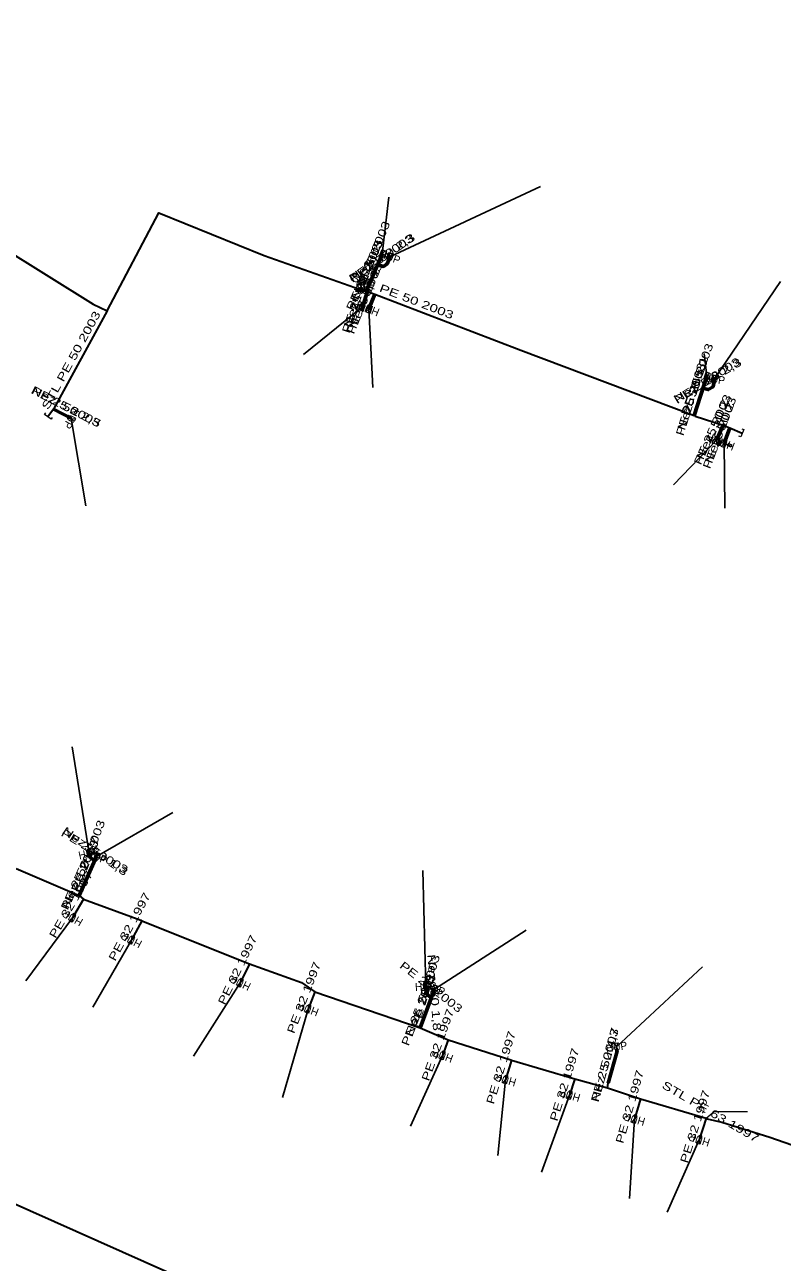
# Model space of a CAD drawing. Extents: x -737484 to -734496, y -1033882 to -1030666.
# Drawn here: x -736052.2 to -735957.6, y -1032940.7 to -1032786.1 of the extents above; entities that cross this region are included whole.
import ezdxf
from ezdxf.enums import TextEntityAlignment as Align

# ---------------------------------------------------------------- set-up
doc = ezdxf.new("R2010")
doc.units = 0
doc.header["$LTSCALE"] = 0.4
for name, color, linetype, lineweight in [('1', 7, 'Continuous', 13), ('18', 7, 'Continuous', 60), ('22', 7, 'Continuous', 25), ('5', 7, 'Continuous', 35), ('7', 7, 'Continuous', 35)]:
    doc.layers.add(name, color=color, linetype=linetype, lineweight=lineweight)
doc.layers.add('2', color=7, linetype='Continuous')

msp = doc.modelspace()

# ---------------------------------------------------------------- linework, layer by layer
at = {"layer": '1'}
for p, q in [((-735964.888, -1032838.359), (-735964.421, -1032838.538)), ((-735964.378, -1032838.635), (-735964.051, -1032838.76)), ((-736001.597, -1032906.297), (-736001.932, -1032906.194)), ((-736001.07, -1032906.537), (-736001.548, -1032906.39))]:
    msp.add_line(p, q, dxfattribs=at)
for points in [[(-736007.586, -1032814.183), (-736007.215, -1032814.333), (-736007.96, -1032815.11), (-736007.589, -1032815.26)], [(-736006.651, -1032814.541), (-736006.278, -1032814.684), (-736007.009, -1032815.475), (-736006.636, -1032815.618)], [(-736010.022, -1032821.856), (-736010.402, -1032821.732), (-736009.713, -1032820.905), (-736010.093, -1032820.781)], [(-736009.264, -1032822.103), (-736009.635, -1032821.953), (-736008.89, -1032821.176), (-736009.261, -1032821.026)], [(-735967.089, -1032829.456), (-735966.711, -1032829.586), (-735967.414, -1032830.401), (-735967.036, -1032830.531)], [(-735966.24, -1032829.832), (-735965.844, -1032829.887), (-735966.379, -1032830.822), (-735965.983, -1032830.877)], [(-736045.891, -1032835.303), (-736046.073, -1032835.66), (-736046.782, -1032834.849), (-736046.964, -1032835.206)], [(-735965.856, -1032838.527), (-735966.222, -1032838.364), (-735965.449, -1032837.613), (-735965.815, -1032837.45)], [(-735964.879, -1032838.897), (-735965.252, -1032838.754), (-735964.521, -1032837.963), (-735964.894, -1032837.82)], [(-735963.954, -1032838.717), (-735964.008, -1032838.857), (-735964.474, -1032838.678), (-735964.421, -1032838.538)], [(-735964.003, -1032838.738), (-735964.03, -1032838.808), (-735964.426, -1032838.656), (-735964.399, -1032838.585)], [(-735963.954, -1032838.717), (-735963.9, -1032838.577), (-735964.367, -1032838.398), (-735964.421, -1032838.538)], [(-736044.524, -1032889.134), (-736044.134, -1032889.044), (-736044.299, -1032890.109), (-736043.909, -1032890.019)], [(-736043.278, -1032889.446), (-736042.905, -1032889.589), (-736043.636, -1032890.38), (-736043.263, -1032890.523)], [(-736046.355, -1032898.168), (-736046.702, -1032897.968), (-736045.855, -1032897.301), (-736046.202, -1032897.101)], [(-736038.977, -1032900.942), (-736039.33, -1032900.754), (-736038.507, -1032900.059), (-736038.86, -1032899.871)], [(-736025.366, -1032906.287), (-736025.725, -1032906.111), (-736024.928, -1032905.388), (-736025.287, -1032905.212)], [(-736002.388, -1032905.717), (-736001.989, -1032905.696), (-736002.336, -1032906.715), (-736001.937, -1032906.694)], [(-736001.114, -1032905.999), (-736000.731, -1032906.116), (-736001.406, -1032906.955), (-736001.023, -1032907.072)], [(-736002.026, -1032906.244), (-736002.07, -1032906.388), (-736001.592, -1032906.534), (-736001.548, -1032906.39)], [(-736002.026, -1032906.244), (-736001.982, -1032906.101), (-736001.504, -1032906.247), (-736001.548, -1032906.39)], [(-736001.979, -1032906.22), (-736001.957, -1032906.148), (-736001.55, -1032906.272), (-736001.572, -1032906.344)], [(-736016.844, -1032909.567), (-736017.217, -1032909.424), (-736016.486, -1032908.633), (-736016.859, -1032908.49)], [(-735978.595, -1032913.288), (-735978.199, -1032913.233), (-735978.456, -1032914.278), (-735978.06, -1032914.223)], [(-736000.042, -1032915.372), (-736000.417, -1032915.235), (-735999.7, -1032914.432), (-736000.075, -1032914.295)], [(-735992.136, -1032918.394), (-735992.519, -1032918.277), (-735991.844, -1032917.438), (-735992.227, -1032917.321)], [(-735984.137, -1032920.326), (-735984.52, -1032920.209), (-735983.845, -1032919.37), (-735984.228, -1032919.253)], [(-735976.031, -1032923.319), (-735976.416, -1032923.209), (-735975.755, -1032922.358), (-735976.14, -1032922.248)], [(-735967.948, -1032925.892), (-735968.328, -1032925.768), (-735967.639, -1032924.941), (-735968.019, -1032924.817)]]:
    msp.add_lwpolyline(points, close=True, dxfattribs=at)
for points in [[(-736048.814, -1032835.155), (-736048.964, -1032835.354), (-736049.763, -1032834.753), (-736049.612, -1032834.553)], [(-735962.657, -1032836.542), (-735962.427, -1032836.639), (-735962.818, -1032837.56), (-735963.048, -1032837.462)], [(-735967.14, -1032922.68), (-735966.134, -1032921.843), (-735961.961, -1032921.843)]]:
    msp.add_lwpolyline(points, dxfattribs=at)
at = {"layer": '18'}
for p, q in [((-736009.584, -1032819.381), (-736007.587, -1032814.721)), ((-736009.424, -1032819.415), (-736010.058, -1032821.319)), ((-736008.502, -1032819.728), (-736009.262, -1032821.565)), ((-735968.646, -1032834.879), (-735967.062, -1032829.994)), ((-736048.66, -1032834.104), (-736046.427, -1032835.255)), ((-735964.999, -1032836.113), (-735965.836, -1032837.989)), ((-735964.169, -1032836.447), (-735964.887, -1032838.359)), ((-736045.451, -1032894.832), (-736043.271, -1032889.985)), ((-736002.865, -1032911.396), (-736001.069, -1032906.536)), ((-735979.376, -1032918.271), (-735978.255, -1032914.276))]:
    msp.add_line(p, q, dxfattribs=at)
for points in [[(-736008.104, -1032816.084), (-736007.449, -1032816.274), (-736006.957, -1032815.939), (-736006.571, -1032814.963)], [(-735967.595, -1032831.464), (-735966.866, -1032831.643), (-735966.274, -1032831.294), (-735966.105, -1032830.289)], [(-736043.517, -1032890.496), (-736044.045, -1032890.131), (-736044.217, -1032889.576)], [(-736001.474, -1032907.613), (-736002.092, -1032907.095), (-736002.162, -1032906.205)]]:
    msp.add_lwpolyline(points, dxfattribs=at)
at = {"layer": '22'}
for p, q in [((-736006.644, -1032815.08), (-735987.84, -1032806.299)), ((-736007.588, -1032814.722), (-736006.781, -1032807.638)), ((-735966.112, -1032830.355), (-735957.857, -1032818.162)), ((-736010.058, -1032821.319), (-736017.442, -1032827.262)), ((-736009.263, -1032821.565), (-736008.771, -1032831.391)), ((-735967.063, -1032829.994), (-735967.368, -1032827.153)), ((-736046.428, -1032835.255), (-736044.61, -1032846.162)), ((-735965.836, -1032837.989), (-735971.199, -1032843.571)), ((-735964.887, -1032838.359), (-735964.799, -1032846.461)), ((-736044.217, -1032889.577), (-736046.313, -1032876.273)), ((-736043.271, -1032889.985), (-736033.77, -1032884.469)), ((-736002.163, -1032906.206), (-736002.514, -1032891.732)), ((-736046.279, -1032897.635), (-736052.127, -1032905.491)), ((-736001.069, -1032906.536), (-735989.632, -1032899.175)), ((-736038.92, -1032900.408), (-736043.748, -1032908.787)), ((-735978.328, -1032913.756), (-735967.59, -1032903.755)), ((-736025.328, -1032905.75), (-736031.18, -1032914.908)), ((-736016.853, -1032909.029), (-736020.071, -1032920.088)), ((-736000.059, -1032914.835), (-736004.066, -1032923.667)), ((-735992.183, -1032917.859), (-735993.145, -1032927.34)), ((-735984.183, -1032919.791), (-735987.707, -1032929.412)), ((-735976.086, -1032922.785), (-735976.692, -1032932.708)), ((-735967.985, -1032925.356), (-735971.985, -1032934.403))]:
    msp.add_line(p, q, dxfattribs=at)
at = {"layer": '5'}
msp.add_line((-735967.14, -1032922.68), (-735967.02, -1032922.75), dxfattribs=at)
for points in [[(-736164.978, -1032743.294), (-736163.22, -1032744.622), (-736144.295, -1032756.82), (-736143.663, -1032757.201), (-736143.285, -1032757.399), (-736123.669, -1032770.149), (-736106.324, -1032781.201), (-736106.054, -1032781.318), (-736105.301, -1032781.762), (-736097.333, -1032786.842), (-736084.708, -1032795.224), (-736075.443, -1032801.061), (-736071.322, -1032803.858), (-736070.031, -1032804.587), (-736068.124, -1032805.517), (-736067.175, -1032806.115), (-736055.501, -1032813.666), (-736043.698, -1032820.973), (-736041.939, -1032821.797)], [(-736041.939, -1032821.797), (-736035.48, -1032809.592), (-736022.335, -1032814.913), (-736009.585, -1032819.382), (-736009.425, -1032819.416), (-736008.503, -1032819.729), (-735990.294, -1032826.724), (-735968.647, -1032834.88), (-735968.483, -1032834.98), (-735965, -1032836.114), (-735964.169, -1032836.448), (-735962.623, -1032837.1)], [(-736041.939, -1032821.797), (-736048.661, -1032834.105), (-736049.364, -1032835.054)], [(-736235.45, -1032828.77), (-736180.2, -1032864.22), (-736120.57, -1032899.77), (-736068.64, -1032926.61), (-736000.29, -1032957.08), (-736038.27, -1033017.25), (-736040.52, -1033020.79), (-736047.44, -1033030.09), (-736048.2, -1033031.22)], [(-736053.32, -1032891.49), (-736045.452, -1032894.832), (-736044.92, -1032895.29), (-736037.75, -1032897.91), (-736037.64, -1032898.03), (-736024.19, -1032903.4), (-736017.69, -1032905.72), (-736016.03, -1032906.89), (-736002.866, -1032911.397), (-735999.35, -1032912.86), (-735991.54, -1032915.39), (-735991.43, -1032915.42), (-735983.55, -1032917.74), (-735979.44, -1032918.854), (-735975.35, -1032920.24), (-735967.14, -1032922.68)], [(-735967.14, -1032922.68), (-735967.02, -1032922.75), (-735965.176, -1032923.15), (-735959.158, -1032925.019), (-735949.736, -1032928.317), (-735941.277, -1032931.246), (-735939.362, -1032931.893), (-735921.803, -1032937.993), (-735921.819, -1032938.099)]]:
    msp.add_lwpolyline(points, dxfattribs=at)
at = {"layer": '7'}
for p, q in [((-736008.167, -1032816.154), (-736007.588, -1032814.722)), ((-736009.585, -1032819.382), (-736008.167, -1032816.154)), ((-736009.425, -1032819.416), (-736010.058, -1032821.319)), ((-736008.503, -1032819.729), (-736009.263, -1032821.565)), ((-735967.57, -1032831.427), (-735967.063, -1032829.994)), ((-735968.647, -1032834.88), (-735967.57, -1032831.427)), ((-736048.661, -1032834.105), (-736046.428, -1032835.255)), ((-735965, -1032836.114), (-735965.836, -1032837.989)), ((-735964.169, -1032836.448), (-735964.887, -1032838.359)), ((-736045.452, -1032894.832), (-736043.471, -1032890.516)), ((-736043.471, -1032890.516), (-736043.271, -1032889.985)), ((-736044.92, -1032895.29), (-736046.279, -1032897.635)), ((-736037.64, -1032898.03), (-736038.919, -1032900.407)), ((-736024.19, -1032903.4), (-736025.327, -1032905.75)), ((-736016.03, -1032906.89), (-736016.852, -1032909.029)), ((-736001.392, -1032907.619), (-736001.069, -1032906.536)), ((-736002.866, -1032911.397), (-736001.392, -1032907.619)), ((-735999.35, -1032912.86), (-736000.059, -1032914.834)), ((-735991.43, -1032915.42), (-735992.182, -1032917.858)), ((-735983.55, -1032917.74), (-735984.183, -1032919.79)), ((-735975.35, -1032920.24), (-735976.086, -1032922.784)), ((-735967.14, -1032922.68), (-735967.984, -1032925.355))]:
    msp.add_line(p, q, dxfattribs=at)
for points in [[(-736008.167, -1032816.154), (-736007.536, -1032816.344), (-736006.98, -1032815.959), (-736006.644, -1032815.08)], [(-735967.57, -1032831.427), (-735966.821, -1032831.594), (-735966.232, -1032831.22), (-735966.112, -1032830.355)], [(-736043.471, -1032890.516), (-736044.081, -1032890.151), (-736044.217, -1032889.577)], [(-736001.392, -1032907.619), (-736002.111, -1032907.063), (-736002.163, -1032906.206)], [(-735979.44, -1032918.854), (-735979.377, -1032918.272), (-735978.256, -1032914.277), (-735978.328, -1032913.756)]]:
    msp.add_lwpolyline(points, dxfattribs=at)

# ---------------------------------------------------------------- texts
at = {"layer": '18', "width": 1.4}
for s, rotation, p in [('Nez. 50 2,3', 34.251, (-736007.3319, -1032815.5887)), ('Nez. 50 5', 66.803, (-736009.0441, -1032816.8539)), ('Nez. 50 2', 71.583, (-736010.2146, -1032820.2085)), ('Nez. 50 2', 67.524, (-736009.3429, -1032820.4546)), ('Nez. 50 2,3', 30.521, (-735966.7074, -1032830.9688)), ('Nez. 50 5,1', 72.034, (-735968.3292, -1032832.2817)), ('Nez. 50 2,5', 332.731, (-736047.3136, -1032834.2349)), ('Nez. 50 2', 65.955, (-735965.8739, -1032836.8467)), ('Nez. 50 2', 69.418, (-735964.9953, -1032837.2268)), ('Nez. 50 1,3', 325.344, (-736043.7353, -1032889.737)), ('Nez. 50 4,7', 65.784, (-736044.8161, -1032892.2031)), ('Nez. 50 1,8', 274.497, (-736001.5968, -1032907.0128)), ('Nez. 50 5', 69.718, (-736002.4354, -1032908.7918)), ('Nez. 50 4,7', 74.326, (-735979.2965, -1032916.1381))]:
    msp.add_text(s, height=1, rotation=rotation, dxfattribs=at).set_placement(p, align=Align.CENTER)
at = {"layer": '2', "width": 0.95}
for rotation, p in [(338, (-736007.7748, -1032815.185)), (339, (-736006.8227, -1032815.5463)), (162, (-736009.903, -1032820.843)), (158, (-736009.0752, -1032821.101)), (341, (-735967.2253, -1032830.466)), (352, (-735966.1811, -1032830.8497)), (243, (-736046.8735, -1032835.0275)), (156, (-735965.6321, -1032837.5313)), (159, (-735964.7073, -1032837.8917)), (13, (-736044.104, -1032890.0635)), (339, (-736043.4497, -1032890.4513)), (150, (-736046.0285, -1032897.2019)), (152, (-736038.6838, -1032899.965)), (154, (-736025.1073, -1032905.3005)), (3, (-736002.1357, -1032906.7045)), (343, (-736001.2147, -1032907.0138)), (159, (-736016.6723, -1032908.5617)), (8, (-735978.2581, -1032914.2503)), (160, (-735999.8875, -1032914.3633)), (163, (-735992.0353, -1032917.3792)), (163, (-735984.0363, -1032919.3112)), (164, (-735975.9477, -1032922.3032)), (162, (-735967.829, -1032924.879))]:
    msp.add_text('HUP', height=1, rotation=rotation, dxfattribs=at).set_placement(p, align=Align.CENTER)
at = {"layer": '5', "width": 1.4}
for s, rotation, p in [('STL PE 50 2003', 338.986, (-736005.3223, -1032820.4143)), ('STL PE 50 2003', 61.359, (-736046.0219, -1032828.2292)), ('STL PE 63 1997', 329.744, (-735966.8279, -1032922.2828))]:
    msp.add_text(s, height=1, rotation=rotation, dxfattribs=at).set_placement(p, align=Align.CENTER)
at = {"layer": '7', "width": 1.35}
for s, rotation, p in [('PE 25 2003', 67.985, (-736008.3401, -1032815.2499)), ('PE 25 2003', 66.285, (-736009.3331, -1032817.5666)), ('PE 25 2003', 34.701, (-736007.4266, -1032815.6601)), ('PE 25 2003', 71.601, (-736010.2153, -1032820.2093)), ('PE 25 2003', 67.513, (-736009.3447, -1032820.4552)), ('PE 25 2003', 70.516, (-735967.7875, -1032830.5433)), ('PE 25 2003', 32.415, (-735966.7495, -1032830.9554)), ('PE 25 2003', 72.677, (-735968.5851, -1032833.0039)), ('PE 25 2003', 332.751, (-736047.3149, -1032834.235)), ('PE 25 2003', 65.97, (-735965.8738, -1032836.8471)), ('PE 25 2003', 69.408, (-735964.9952, -1032837.2269)), ('PE 25 2003', 69.361, (-736043.8384, -1032890.0737)), ('PE 25 2003', 329.105, (-736043.7717, -1032889.7522)), ('PE 25 2003', 65.345, (-736044.9151, -1032892.4646)), ('PE 32 1997', 59.906, (-736046.0319, -1032896.2112)), ('PE 32 1997', 61.716, (-736038.7191, -1032898.9809)), ('PE 32 1997', 64.181, (-736025.2077, -1032904.3568)), ('PE 25 2003', 73.393, (-736001.7095, -1032906.9344)), ('PE 32 1997', 68.979, (-736016.9075, -1032907.7794)), ('PE 25 2003', 322.285, (-736001.7849, -1032906.6825)), ('PE 25 2003', 68.687, (-736002.5949, -1032909.3257)), ('PE 32 1997', 70.243, (-736000.1748, -1032913.6775)), ('PE 32 1997', 72.858, (-735992.2836, -1032916.4914)), ('PE 25 2003', 74.326, (-735979.3055, -1032916.1676)), ('PE 32 1997', 72.84, (-735984.3442, -1032918.617)), ('PE 32 1997', 73.864, (-735976.1974, -1032921.3725)), ('PE 32 1997', 72.489, (-735968.038, -1032923.8664))]:
    msp.add_text(s, height=1, rotation=rotation, dxfattribs=at).set_placement(p, align=Align.CENTER)

doc.saveas('drawing.dxf')
